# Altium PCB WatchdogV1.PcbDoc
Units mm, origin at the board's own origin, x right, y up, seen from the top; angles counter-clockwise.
Board outline 200 x 52 mm, 2 copper layers (Top Layer, Bottom Layer), stack 1.57 mm thick; 69 components, 43 nets, 240 pads, 392 vias.
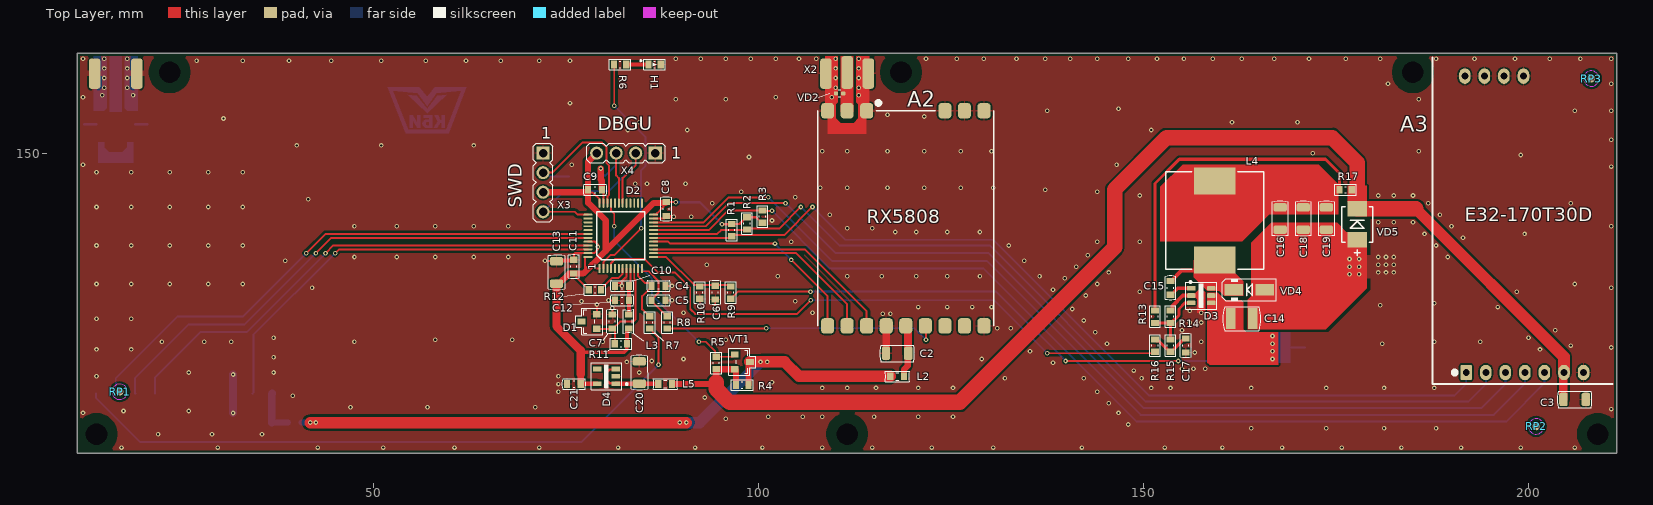
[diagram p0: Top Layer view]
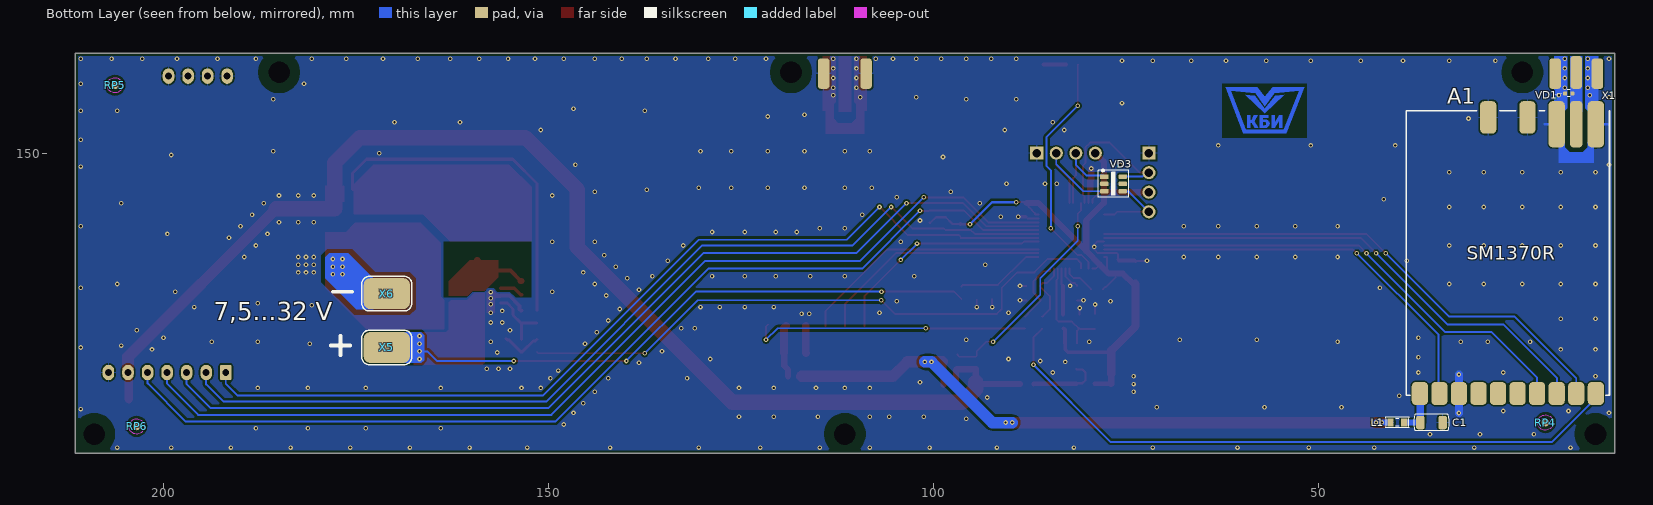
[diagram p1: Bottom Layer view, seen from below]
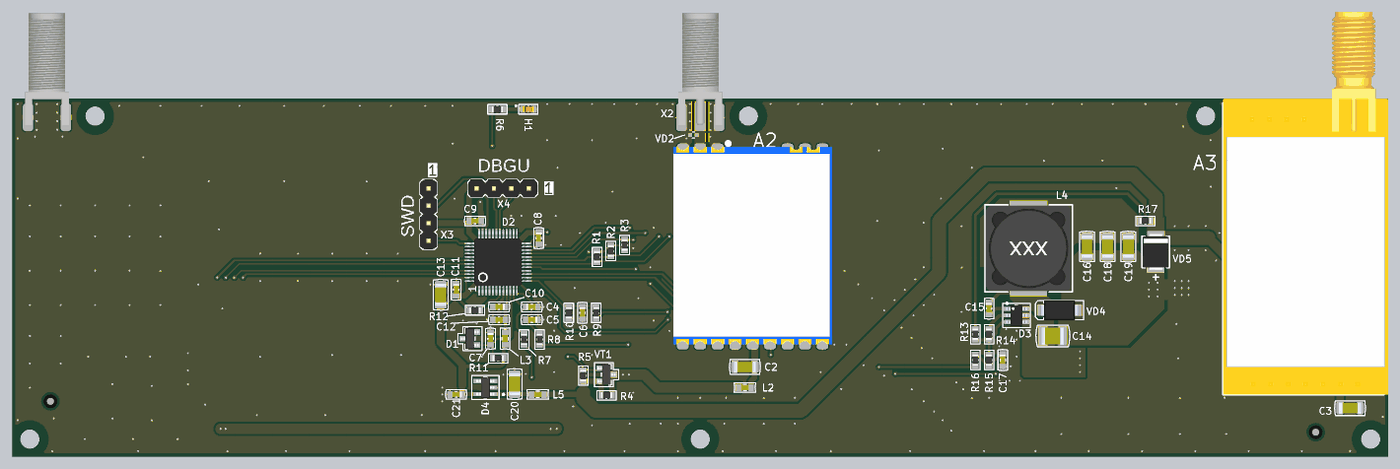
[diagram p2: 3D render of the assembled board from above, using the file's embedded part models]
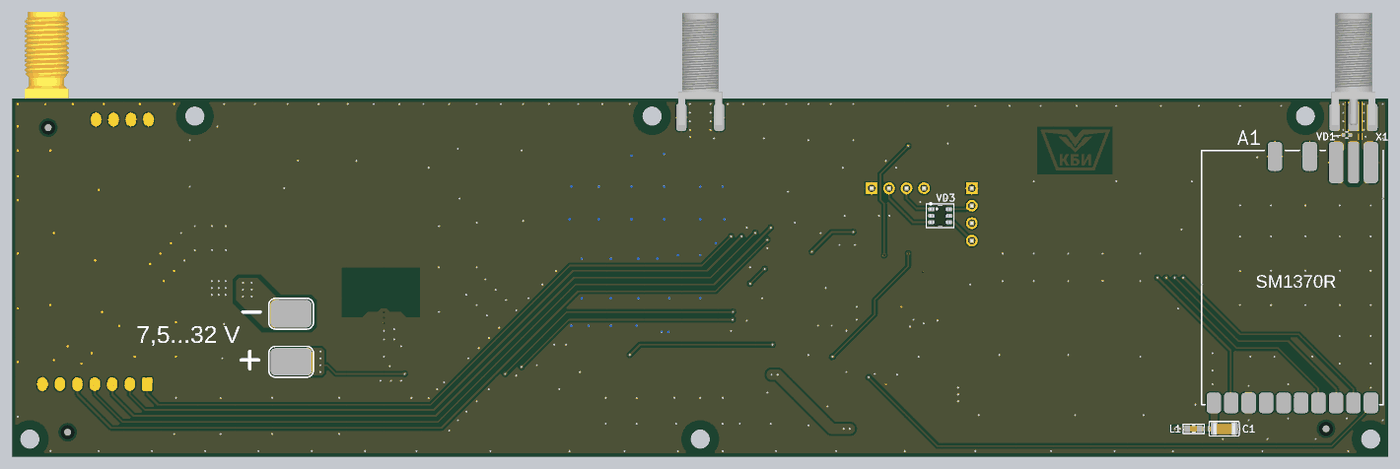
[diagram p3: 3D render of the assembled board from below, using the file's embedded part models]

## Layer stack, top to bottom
Top Solder: solder mask 0.0102, Solder Resist, Dk 3.5
Top Layer: signal copper 0.035
Dielectric 1: core 1.5, FR4 Tg135, Dk 4.5
Bottom Layer: signal copper 0.035
Bottom Solder: solder mask 0.0102, Solder Resist, Dk 3.5

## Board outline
11.5,111 211.5,111 211.5,163 11.5,163

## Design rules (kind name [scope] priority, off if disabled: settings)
AcuteAngle [All] p1: minimum=3.50000000000000E+0001 checktracksonly=FALSE
BoardOutlineClearance "BoardOutlineClearance 1" [All] p1 off: gap=0.25 ignorepadtopadclearanceinfootprint=FALSE except(0: Arc-SplitContinuation Track-SplitContinuation SMDPad-SplitContinuation THPad-SplitContinuation Via-SplitContinuation Fill-SplitContinuation Poly-SplitContinuation Region-SplitContinuation Text-SplitContinuation) // Milling
BoardOutlineClearance "BoardOutlineClearance 2" [All] p2: gap=0.4 ignorepadtopadclearanceinfootprint=FALSE except(0: Arc-SplitContinuation Track-SplitContinuation SMDPad-SplitContinuation THPad-SplitContinuation Via-SplitContinuation Fill-SplitContinuation Poly-SplitContinuation Region-SplitContinuation Text-SplitContinuation) // V-Cut
Clearance "Clearance 3 Oz" [All] p1 off: gap=0.35 ignorepadtopadclearanceinfootprint=FALSE except(0.25: Arc-Hole Track-Hole SMDPad-Hole THPad-Hole Via-Hole Fill-Hole Poly-Hole Region-Hole Text-Hole)
Clearance "Clearance 2 Oz" [All] p2 off: gap=0.3 ignorepadtopadclearanceinfootprint=FALSE except(0.25: Arc-Hole Track-Hole SMDPad-Hole THPad-Hole Via-Hole Fill-Hole Poly-Hole Region-Hole Text-Hole)
Clearance "Clearance-1 1 Oz" [All] p3: gap=0.2 ignorepadtopadclearanceinfootprint=FALSE except(0.25: Arc-Hole Track-Hole SMDPad-Hole THPad-Hole Via-Hole Fill-Hole Poly-Hole Region-Hole Text-Hole; 0.3: Arc-Fill Arc-Poly Arc-Region Track-Fill Track-Poly Track-Region Fill-Fill Fill-Poly Fill-Region Poly-Poly Poly-Region Region-Region) // Standart
Clearance "Clearance-2 1 Oz" [All] p4 off: gap=0.15 ignorepadtopadclearanceinfootprint=FALSE except(0.2: Arc-Fill Arc-Poly Track-Fill Track-Poly SMDPad-Fill SMDPad-Poly THPad-Fill THPad-Poly Via-Fill Via-Poly Fill-Fill Fill-Poly Poly-Poly; 0.25: Arc-Hole Track-Hole SMDPad-Hole THPad-Hole Via-Hole Fill-Hole Poly-Hole Region-Hole Text-Hole) // Advance
Clearance "Clearance-1 1/2 Oz" [All] p5 off: gap=0.125 ignorepadtopadclearanceinfootprint=FALSE except(0.2: Arc-Fill Arc-Poly Track-Fill Track-Poly SMDPad-SMDPad SMDPad-Fill SMDPad-Poly THPad-Fill THPad-Poly Via-Fill Via-Poly Fill-Fill Fill-Poly Poly-Poly Poly-Region Poly-Text; 0.25: Arc-Hole Track-Hole SMDPad-Hole THPad-Hole Via-Hole Fill-Hole Poly-Hole Region-Hole Text-Hole) // Standart
Clearance "Clearance-2 1/2 Oz" [All] p6 off: gap=0.1 ignorepadtopadclearanceinfootprint=FALSE except(0.15: Arc-Fill Arc-Poly Track-Fill Track-Poly SMDPad-SMDPad SMDPad-Fill SMDPad-Poly THPad-Fill THPad-Poly Via-Fill Via-Poly Fill-Fill Fill-Poly Poly-Poly Poly-Region Poly-Text; 0.25: Arc-Hole Track-Hole SMDPad-Hole THPad-Hole Via-Hole Fill-Hole Poly-Hole Region-Hole Text-Hole) // Advance
DiffPairsRouting "DiffPairsRouting 1 Oz" [All] p1: maxlimit=0.254 minlimit=0.2 mostfreqgap=0.254 toplayer_minwidth=0.2 toplayer_maxwidth=0.381 toplayer_prefwidth=0.381 bottomlayer_minwidth=0.2 bottomlayer_maxwidth=0.381 bottomlayer_prefwidth=0.381 maxuncoupledlength=12.7
DiffPairsRouting "DiffPairsRouting 1/2 Oz" [All] p2 off: maxlimit=0.254 minlimit=0.1 mostfreqgap=0.254 toplayer_minwidth=0.1 toplayer_maxwidth=0.381 toplayer_prefwidth=0.381 bottomlayer_minwidth=0.1 bottomlayer_maxwidth=0.381 bottomlayer_prefwidth=0.381 maxuncoupledlength=12.7
HoleSize "Minimum HoleSize" [IsPad] p1: absolutevalues=TRUE maxlimit=5.9 minlimit=0.6 maxpercent=80.000 minpercent=20.000
HoleSize "Minimum HoleSize VIA 1" [IsVia] p2: absolutevalues=TRUE maxlimit=5.9 minlimit=0.3 maxpercent=80.000 minpercent=20.000 // Standart
HoleSize "Minimum HoleSize VIA 2" [IsVia] p3 off: absolutevalues=TRUE maxlimit=5.9 minlimit=0.2 maxpercent=80.000 minpercent=20.000 // Advance
HoleToHoleClearance Hole2HoleClearance [All] p1: gap=0.25 allowstackedmicrovias=FALSE
MinimumAnnularRing "Minimum AR VIA Standart" [IsVia] p1: minimumring=0.15
MinimumAnnularRing "Minimum AR PAD Standart" [IsPAD] p2: minimumring=0.2
MinimumAnnularRing "Minimum AR VIA Advance" [IsVia] p3 off: minimumring=0.1
MinimumAnnularRing "Minimum AR PAD Advance" [IsPAD] p4 off: minimumring=0.15
MinimumSolderMaskSliver "SolderMask Bridge Standart" [All] p1: minsoldermaskwidth=0.15 // All Masks
MinimumSolderMaskSliver "SolderMask Bridge Advance" [All] p2: minsoldermaskwidth=0.1 // Mask LDI
PlaneClearance "PlaneClearance 3 Oz" [All] p1 off: clearance=0.35
PlaneClearance "PlaneClearance 2 Oz" [All] p2 off: clearance=0.3
PlaneClearance "PlaneClearance 1 Oz" [All] p3: clearance=0.2
PlaneClearance "PlaneClearance-1 1/2 Oz" [All] p4 off: clearance=0.2 // Standart
PlaneClearance "PlaneClearance-2 1/2 Oz" [All] p5 off: clearance=0.15 // Advance
PlaneConnect "TermalConnect 3 Oz" [All] p1 off: planeconnectstyle=Relief reliefexpansion=0.2 reliefentries=4 reliefconductorwidth=0.35 reliefairgap=0.35 // Standart
PlaneConnect "TermalConnect 2 Oz" [All] p2 off: planeconnectstyle=Relief reliefexpansion=0.2 reliefentries=4 reliefconductorwidth=0.3 reliefairgap=0.3 // Standart
PlaneConnect "TermalConnect-1 1 Oz" [All] p3: planeconnectstyle=Relief reliefexpansion=0.2 reliefentries=4 reliefconductorwidth=0.2 reliefairgap=0.2 // Standart
PlaneConnect "TermalConnect-2 1 Oz" [All] p4 off: pad.planeconnectstyle=Relief pad.reliefexpansion=0.15 pad.reliefentries=4 pad.reliefconductorwidth=0.2 pad.reliefairgap=0.2 via.planeconnectstyle=Direct via.reliefexpansion=0.15 via.reliefentries=4 via.reliefconductorwidth=0.15 via.reliefairgap=0.15 // Advance
PlaneConnect "TermalConnect-1 1/2 Oz" [All] p5 off: planeconnectstyle=Relief reliefexpansion=0.2 reliefentries=4 reliefconductorwidth=0.2 reliefairgap=0.2 // Standart
PlaneConnect "TermalConnect-2 1/2 Oz" [All] p6 off: pad.planeconnectstyle=Relief pad.reliefexpansion=0.15 pad.reliefentries=4 pad.reliefconductorwidth=0.15 pad.reliefairgap=0.15 via.planeconnectstyle=Direct via.reliefexpansion=0.15 via.reliefentries=4 via.reliefconductorwidth=0.15 via.reliefairgap=0.15 // Advance
PolygonConnect "PolygonConnect 3 Oz" [All] p1 off: thpad.connectstyle=Relief thpad.reliefconductorwidth=0.35 thpad.reliefentries=4 thpad.polygonreliefangle="90 Angle" thpad.airgapwidth=0.35 smdpad.connectstyle=Relief smdpad.reliefconductorwidth=0.35 smdpad.reliefentries=4 smdpad.polygonreliefangle="90 Angle" smdpad.airgapwidth=0.35 via.connectstyle=Direct via.reliefconductorwidth=0.254 via.reliefentries=4 via.polygonreliefangle="90 Angle" via.airgapwidth=0.254
PolygonConnect "PolygonConnect 2 Oz" [All] p2 off: thpad.connectstyle=Relief thpad.reliefconductorwidth=0.3 thpad.reliefentries=4 thpad.polygonreliefangle="90 Angle" thpad.airgapwidth=0.3 smdpad.connectstyle=Relief smdpad.reliefconductorwidth=0.3 smdpad.reliefentries=4 smdpad.polygonreliefangle="90 Angle" smdpad.airgapwidth=0.3 via.connectstyle=Direct via.reliefconductorwidth=0.254 via.reliefentries=4 via.polygonreliefangle="90 Angle" via.airgapwidth=0.254
PolygonConnect "PolygonConnect-1 1 Oz" [All] p3: thpad.connectstyle=Relief thpad.reliefconductorwidth=0.2 thpad.reliefentries=4 thpad.polygonreliefangle="90 Angle" thpad.airgapwidth=0.2 smdpad.connectstyle=Relief smdpad.reliefconductorwidth=0.2 smdpad.reliefentries=4 smdpad.polygonreliefangle="90 Angle" smdpad.airgapwidth=0.2 via.connectstyle=Direct via.reliefconductorwidth=0.254 via.reliefentries=4 via.polygonreliefangle="90 Angle" via.airgapwidth=0.254 // Standart
PolygonConnect "PolygonConnect-2 1 Oz" [All] p4 off: thpad.connectstyle=Relief thpad.reliefconductorwidth=0.15 thpad.reliefentries=4 thpad.polygonreliefangle="90 Angle" thpad.airgapwidth=0.15 smdpad.connectstyle=Relief smdpad.reliefconductorwidth=0.15 smdpad.reliefentries=4 smdpad.polygonreliefangle="90 Angle" smdpad.airgapwidth=0.15 via.connectstyle=Direct via.reliefconductorwidth=0.254 via.reliefentries=4 via.polygonreliefangle="90 Angle" via.airgapwidth=0.254 // Advance
PolygonConnect "PolygonConnect-1 1/2 Oz" [All] p5 off: thpad.connectstyle=Relief thpad.reliefconductorwidth=0.15 thpad.reliefentries=4 thpad.polygonreliefangle="90 Angle" thpad.airgapwidth=0.2 smdpad.connectstyle=Relief smdpad.reliefconductorwidth=0.2 smdpad.reliefentries=4 smdpad.polygonreliefangle="90 Angle" smdpad.airgapwidth=0.2 via.connectstyle=Direct via.reliefconductorwidth=0.254 via.reliefentries=4 via.polygonreliefangle="90 Angle" via.airgapwidth=0.254 // Standart
PolygonConnect "PolygonConnect-2 1/2 Oz" [All] p6 off: thpad.connectstyle=Relief thpad.reliefconductorwidth=0.125 thpad.reliefentries=4 thpad.polygonreliefangle="90 Angle" thpad.airgapwidth=0.15 smdpad.connectstyle=Relief smdpad.reliefconductorwidth=0.125 smdpad.reliefentries=4 smdpad.polygonreliefangle="90 Angle" smdpad.airgapwidth=0.15 via.connectstyle=Direct via.reliefconductorwidth=0.254 via.reliefentries=4 via.polygonreliefangle="90 Angle" via.airgapwidth=0.254 // Advance
RoutingCorners [All] p1 off: cornerstyle=45-Degree minsetback=2.54 maxsetback=2.54
RoutingVias [All] p1: holewidth=0.3 width=0.6 viastyle="Through Hole" minholewidth=0.2 minwidth=0.4 maxholewidth=5.9 maxwidth=6.4
SilkToSilkClearance Silk2SilkClearance [All] p1 off: silktosilkclearance=0.15
SilkToSolderMaskClearance Silk2SolderMaskClearance [IsPad] p1 off: minsilkscreentomaskgap=0.15 clearancetoexposedcopper=TRUE
SolderMaskExpansion SolderMaskExpansion-1 [All] p1: expansion=0.05 istentingtop=FALSE // Standart
SolderMaskExpansion "SolderMaskExpansion LDI" [All] p2: expansion=0.025 istentingtop=FALSE // Advance
UnRoutedNet [All] p1: checkbadconnections=TRUE
Width "Width 3 Oz" [All] p1 off: maxlimit=10 minlimit=0.35 preferedwidth=0.4 checkconnectedcopper=TRUE
Width "Width 2 Oz" [All] p2 off: maxlimit=10 minlimit=0.3 preferedwidth=0.35 minimp=50.000000 maximp=50.000000 favimp=50.000000 checkconnectedcopper=TRUE
Width "Width 1 Oz" [All] p3: maxlimit=10 minlimit=0.15 preferedwidth=0.2 checkconnectedcopper=TRUE
Width "Width 1/2 Oz" [All] p4 off: maxlimit=10 minlimit=0.1 preferedwidth=0.125 checkconnectedcopper=TRUE
20 further rules are at their usual default settings.

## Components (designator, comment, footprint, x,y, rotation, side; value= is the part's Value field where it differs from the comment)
A1 "Receiver SM1370R" SM1370R 36.82,118.774 r180 bottom locked
A2 "Receiver RX5808" RX5808 108.96,155.5 r0 top locked
A3 "Wireless Module E32-170T30D" E32-170T30D 199.54,121.5 r0 top locked
C1 "Конденсатор керамический 1206-X7R-25V-10uF±10%" CC1206 35.3,115 r180 bottom value=10uF
C2 "Конденсатор керамический 1206-X7R-25V-10uF±10%" CC1206 118,124 r180 top value=10uF
C3 "Конденсатор керамический 1206-X7R-25V-10uF±10%" CC1206 206,118 r0 top value=10uF
C4 "Конденсатор керамический 0603-NP0-50V-1000pF±5%" CC0603 87,132.75 r180 top value=1000pF
C5 "Конденсатор керамический 0603-NP0-50V-1000pF±5%" CC0603 87,130.875 r180 top value=1000pF
C6 "Конденсатор керамический 0603-X7R-50V-0.1uF±10%" CC0603 94.375,131.875 r90 top value=0.1uF
C7 "Конденсатор керамический 0603-X7R-50V-0.1uF±10%" CC0603 81,128.125 r270 top value=0.1uF
C8 "Конденсатор керамический 0603-X7R-50V-0.1uF±10%" CC0603 88,142.75 r270 top value=0.1uF
C9 "Конденсатор керамический 0603-X7R-50V-0.1uF±10%" CC0603 78.75,145.25 r0 top value=0.1uF
C10 "Конденсатор керамический 0603-X7R-50V-0.1uF±10%" CC0603 82.25,132.75 r180 top value=0.1uF
C11 "Конденсатор керамический 0603-X7R-50V-0.1uF±10%" CC0603 76,135.25 r90 top value=0.1uF
C12 "Конденсатор керамический 0603-X7R-16V-1uF±20%" CC0603 82.25,130.875 r180 top value=1uF
C13 "Конденсатор керамический 1206-X7R-25V-10uF±10%" CC1206 73.75,134.5 r90 top value=10uF
C14 "Конденсатор керамический 1210-X7R-63V-10uF±10%" CC1210 162.75,128.5 r0 top value=10uF
C15 "Конденсатор керамический 0603-X7R-50V-0.1uF±10%" CC0603 153.5,132.5 r270 top value=0.1uF
C16 "Конденсатор керамический 1206-X7R-25V-10uF±10%" CC1206 167.75,141.5 r270 top value=10uF
C17 "Конденсатор керамический 0603-X7R-16V-1uF±20%" CC0603 155.5,125 r270 top value=1uF
C18 "Конденсатор керамический 1206-X7R-25V-10uF±10%" CC1206 170.75,141.5 r270 top value=10uF
C19 "Конденсатор керамический 1206-X7R-25V-10uF±10%" CC1206 173.75,141.5 r270 top value=10uF
C20 "Конденсатор керамический 1206-X7R-25V-10uF±10%" CC1206 84.5,121.5 r90 top value=10uF
C21 "Конденсатор керамический 0603-X7R-16V-1uF±20%" CC0603 76,120 r180 top value=1uF
D1 "Микросхема LM4040AIM3-3.0" SOT-23 78,128.125 r180 top
D2 "Микросхема GD32E103CBT6" LQFP48_7x7 79.35,135 r90 top
D3 "Микросхема LMR14010ADDC" SOT-23-6#1 157.499,131.5 r0 top
D4 "Микросхема NCP114ASN330T1G" TSOP-5 80.25,121 r180 top value=3.3V
H1 "Светодиод 0603-RED-[100-150]-[50-150]MCD" LED0603_Red 86.5,161.5 r0 top value="100 MCD Red"
L1 "Дроссель BLM18PG331SN1D" CL0603 39.75,115 r0 bottom value=330R
L2 "Дроссель BLM18PG331SN1D" CL0603 118,121 r180 top value=330R
L3 "Дроссель BLM18AG102SN1D" CL0603 83.125,128.125 r270 top value=1000R
L4 "Дроссель SRR1260-470M" SRR1260 159.25,141.25 r90 top value="47 uH"
L5 "Дроссель BLM18AG102SN1D" CL0603 87.875,120 r180 top value=1000R
R1 "Резистор 0603-0.1W-47K±5%" CR0603 96.5,140 r90 top value=47K
R2 "Резистор 0603-0.1W-47K±5%" CR0603 98.5,140.875 r90 top value=47K
R3 "Резистор 0603-0.1W-47K±5%" CR0603 100.5,141.75 r270 top value=47K
R4 "Резистор 0603-0.1W-0R" CR0603 97.875,119.875 r0 top value=0
R5 "Резистор 0603-0.1W-47K±5%" CR0603 94.5,122.75 r90 top value=47K
R6 "Резистор 0603-0.1W-120R±5%" CR0603 82.001,161.5 r180 top value=120
R7 "Резистор 0603-0.1W-1K±5%" CR0603 85.875,128 r90 top value=1K
R8 "Резистор 0603-0.1W-1K±5%" CR0603 88.125,128 r90 top value=1K
R9 "Резистор 0603-0.1W-33K±1%" CR0603 96.375,131.875 r90 top value=33K
R10 "Резистор 0603-0.1W-3.9K±1%" CR0603 92.375,131.875 r90 top value=3.9K
R11 "Резистор 0603-0.1W-200R±5%" CR0603 82.125,125.25 r180 top value=200
R12 "Резистор 0603-0.1W-1K±5%" CR0603 78.75,132.25 r180 top value=1K
R13 "Резистор 0603-0.1W-43K±1%" CR0603 151.5,128.75 r90 top value=43K
R14 "Резистор 0603-0.1W-10K±1%" CR0603 153.5,128.75 r90 top value=10K
R15 "Резистор 0603-0.1W-36K±1%" CR0603 153.5,125 r270 top value=36K
R16 "Резистор 0603-0.1W-200R±5%" CR0603 151.5,125 r270 top value=200
R17 "Резистор 0603-0.1W-0R" CR0603 176.25,145.25 r0 top value=0
RP1 "Reper" Reper-Min 17,119 r0 top
RP2 "Reper" Reper-Min 201,114.5 r0 top
RP3 "Reper" Reper-Min 208.179,159.681 r0 top
RP4 "Reper" Reper-Min 20.5,115 r180 bottom
RP5 "Reper" Reper-Min 206.321,158.819 r180 bottom
RP6 "Reper" Reper-Min 203.5,114.5 r180 bottom
VD1 "Диод ESDAXLC6-1BT2" ESDAXLC6-1BT2 17.95,157.75 r180 bottom locked
VD2 "Диод ESDAXLC6-1BT2" ESDAXLC6-1BT2 110.05,157.75 r0 top locked
VD3 "Диодная сборка ESDA6V1BC6" SOT-23-6#2 76.6,146 r180 bottom
VD4 "Диод MBRA340T3G" "DO-214AC (SMA)" 163.75,132.25 r180 top
VD5 "Диод SMBJ5.0A" DO-214AA 177.75,140.75 r90 top
VT1 "Транзистор AO3401A" SOT-23 97.874,122.875 r0 top
X1 "Розетка KLS1-SMA060" SMA_Edge 16.5,160.475 r180 bottom locked
X2 "Розетка KLS1-SMA060" SMA_Edge 111.5,160.475 r0 top locked
X3 "Вилка PLS-4" PLS-4 72,150 r270 top
X4 "Вилка PLS-4" PLS-4 86.58,150 r180 top
X5 "Паяный контакт" PD-6X4 171,124.75 r270 bottom
X6 "Паяный контакт" PD-6X4 171,131.75 r270 bottom

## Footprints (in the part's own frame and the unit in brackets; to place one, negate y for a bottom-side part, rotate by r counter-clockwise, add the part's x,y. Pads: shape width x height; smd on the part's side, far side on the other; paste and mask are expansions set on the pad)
CC0603 [mm]
  rect 0.8x1 smd: 1(-0.9,0) 2(0.9,0)
  silkscreen extent -1.54,-0.71 1.54,0.7, body extent -0.81,-0.42 0.81,0.43, height 0.46
CC1206 [mm]
  rrect50% 1.1x1.75 smd: 1(-1.45,0) 2(1.45,0)
  silkscreen extent -2.25,-1.07 2.25,1.07, body extent -1.6,-0.8 1.6,0.8, height 1.3
CC1210 [mm]
  rect 1.25x2.75 smd: 1(-1.425,0) 2(1.425,0)
  silkscreen extent -2.44,-1.57 2.5,1.57, body extent -1.6,-1.25 1.6,1.25, height 1.3
CL0603 [mm]
  rect 0.8x1 smd: 1(-0.9,0) 2(0.9,0)
  silkscreen extent -1.56,-0.69 1.57,0.69, body extent -0.81,-0.42 0.81,0.43, height 0.46
CR0603 [mm]
  rect 0.8x1 smd: 1(-0.8,0) 2(0.8,0)
  silkscreen extent -1.4,-0.7 1.4,0.7, body extent -0.81,-0.42 0.81,0.43, height 0.46
DO-214AA [mm]
  rect 2x2.5 smd: A(-2,0) K(2,0)
  silkscreen extent -4.1,-2 2.3,2, body extent -2.65,-1.85 2.65,1.85, height 2.2
"DO-214AC (SMA)" [mm] "Molded Diode, 2-Leads, Body 4,2x2,7mm, IPC Medium Density"
  rect 2.4x1.55 smd: 1(-2,0) 2(2,0)
  silkscreen extent -3.5,-1.45 3.5,1.45, body extent -2.8,-1.45 2.8,1.45, height 2.4
E32-170T30D [mm]
  rrect30% 1.5x2 hole 0.9: 1(-7.62,0)
  oval 1.5x2 hole 0.9: 2(-5.08,0) 3(-2.54,0) 4(0,0) 5(2.54,0) 6(5.08,0) 7(7.62,0) 8(-0.18,38.5) 9(-2.72,38.5) 10(-5.26,38.5) 11(-7.8,38.5)
  silkscreen extent -12,-1.5 11.36,40.9, body extent -12,-1.5 12,54.2, height 8.27
ESDAXLC6-1BT2 [mm]
  rrect50% 0.55x0.5 smd: 1(0,0) 2(0.95,0)
  silkscreen extent 0.3,-0.45 0.65,0.45, body extent 0,-0.3 1,0.3, height 0.4
LED0603_Red [mm]
  rect 0.8x1 smd: 1(-0.8,0) 2(0.8,0)
  silkscreen extent -1.9,-0.7 1.4,0.7, body extent -0.81,-0.4 0.81,0.4, height 1.1
LQFP48_7x7 [mm]
  rect 1.2x0.25 smd: 1(0,0)
  oval 1.2x0.25 smd: 2(0,-0.5) 3(0,-1) 4(0,-1.5) 5(0,-2) 6(0,-2.5) 7(0,-3) 8(0,-3.5) 9(0,-4) 10(0,-4.5) 11(0,-5) 12(0,-5.5) 25(8.5,-5.5) 26(8.5,-5) 27(8.5,-4.5) 28(8.5,-4) 29(8.5,-3.5) 30(8.5,-3) 31(8.5,-2.5) 32(8.5,-2) 33(8.5,-1.5) 34(8.5,-1) 35(8.5,-0.5) 36(8.5,0)
  oval 0.25x1.2 smd: 13(1.5,-7) 14(2,-7) 15(2.5,-7) 16(3,-7) 17(3.5,-7) 18(4,-7) 19(4.5,-7) 20(5,-7) 21(5.5,-7) 22(6,-7) 23(6.5,-7) 24(7,-7) 37(7,1.5) 38(6.5,1.5) 39(6,1.5) 40(5.5,1.5) 41(5,1.5) 42(4.5,1.5) 43(4,1.5) 44(3.5,1.5) 45(3,1.5) 46(2.5,1.5) 47(2,1.5) 48(1.5,1.5)
  silkscreen extent 1.13,-5.86 7.36,0.37, body extent -0.25,-7.25 8.75,1.75, height 1.2
PD-6X4 [mm]
  rrect40% 4x6 smd: 1(0,0)
  silkscreen extent -2.25,-3.25 2.25,3.25
PLS-4 [mm]
  rect 1.7x1.7 hole 1.1: 1(0,0)
  round 1.7 hole 1.1: 2(2.54,0) 3(5.08,0) 4(7.62,0)
  silkscreen extent -1.27,-1.27 8.89,1.27, body extent -1.27,-1.27 8.89,1.27, height 8.8
Reper-Min [mm]
  round 1 smd mask+0.5: 0(0,0)
  Top Layer keep-out circle w0.1: c0,0 r1
RX5808 [mm]
  rrect50% 1.7x2 smd: 1(5.08,0) 1(15.24,0) 1(17.78,0) 1(20.32,0) 2(2.54,0) 3(0,0) 4(0,-27.94) 5(2.54,-27.94) 6(5.08,-27.94) 7(7.62,-27.94) 8(10.16,-27.94) 9(12.7,-27.94) 10(15.24,-27.94) 11(17.78,-27.94) 12(20.32,-27.94)
  silkscreen extent -1.27,-27.94 21.59,1.27, body extent -1.39,-28.19 21.71,0.51, height 3.11
SM1370R [mm]
  rrect50% 1.6x6 smd: 1(20.32,34.976)
  rrect50% 2.1x4.2 smd: 2(8.89,35.865) 2(13.97,35.865)
  rrect50% 2.1x6 smd: 2(17.78,34.976) 2(22.86,34.976)
  rrect50% 2.1x3 smd: 3(0,0) 4(2.54,0) 5(5.08,0) 6(7.62,0) 7(10.16,0) 8(12.7,0) 9(15.24,0) 10(17.78,0) 11(20.32,0) 12(22.86,0)
  silkscreen extent -1.78,-0.25 24.64,36.75, body extent -1.75,-0.25 24.65,36.75, height 3.3
SMA_Edge [mm] "Монтаж с торца платы"
  rrect50% 1.5x4.25 smd: 1(0,0)
  rrect50% 1.5x3.95 smd far side: 2(-2.75,-0.15) 2(2.75,-0.15)
  rrect50% 1.5x3.95 smd: 2(-2.75,-0.15) 2(2.75,-0.15)
  body extent -3.17,-1.3 3.18,14.96, height 3.83
SOT-23 [mm]
  rect 1x0.8 smd: 1(-0.975,0.95) 2(-0.975,-0.95) 3(1,0)
  silkscreen extent -1.75,-1.75 1.75,1.75, body extent -1.3,-1.5 1.3,1.5, height 1.12
SOT-23-6#1 [mm]
  rect 1.1x0.6 smd: 1(-1.3,0.95)
  rrect50% 1.1x0.6 smd: 2(-1.3,0) 3(-1.3,-0.95) 4(1.3,-0.95) 5(1.3,0) 6(1.3,0.95)
  silkscreen extent -2,-1.75 2,1.87, body extent -1.5,-1.52 1.5,1.52, height 1.45
SOT-23-6#2 [mm]
  rect 1.1x0.6 smd: 1(-1.2,0.95)
  rrect50% 1.1x0.6 smd: 2(-1.2,0) 3(-1.2,-0.95) 4(1.2,-0.95) 5(1.2,0) 6(1.2,0.95)
  silkscreen extent -2,-1.75 2,1.87, body extent -1.5,-1.52 1.5,1.53, height 1.45
SRR1260 [mm]
  rect 3.5x5.4 smd: 1(-5.15,0) 2(5.15,0)
  silkscreen extent -6.35,-6.35 6.35,6.35, body extent -6.25,-6.25 6.25,6.25, height 6.5
TSOP-5 [mm] "(SOT23-5)"
  rect 1.1x0.6 smd: 1(-1.2,0.95) 2(-1.2,0) 3(-1.2,-0.95) 4(1.2,-0.95) 5(1.2,0.95)
  silkscreen extent -2.75,-1.75 2,1.75, body extent -1.3,-1.5 1.3,1.5, height 1.12

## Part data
A1: library part SM1370R, "Аналоговый видеоприемник 1,2 ГГц"
A2: library part RX5808, "Аналоговый видеоприемник 5,8 ГГц"
A3: library part E32-170T30D, "Приемопередатчик 170 МГц"
C1 C2 C3 C13 C16 C18 C19 C20: library part CC1206-X7R-25V-10uF±10%, "Конденсатор керамический SMD", Manufacturer=Murata, Supplier Part Number 1=490-6518-6-ND
C4 C5: library part CC0603-NP0-50V-1000pF±5%, "Конденсатор керамический SMD", Manufacturer=Murata
C6 C7 C8 C9 C10 C11 C15: library part CC0603-X7R-50V-0.1uF±10%, "Конденсатор керамический SMD", Manufacturer=Samsung, Supplier Part Number 1=1276-1000-1-ND
C12 C17 C21: library part CC0603-X7R-16V-1uF±20%, "Конденсатор керамический SMD", Manufacturer=Samsung, Supplier Part Number 1=1276-6524-1-ND
C14: library part CC1210-X7R-50V-10uF±20%, "Конденсатор керамический SMD", Manufacturer=Murata
D1: library part LM4040AIM3-3.0, "ИОН 3.0V±0.1%; -40...+85C", Manufacturer=TI, Package=SOT-23
D2: library part GD32E103Cxxx, "ARM Cortrex-M4", Manufacturer=GigaDevice
D3: library part LMR14010ADDC, "DC/DC понижающий", Manufacturer=TI
D4: library part NCP114ASN330T, "LDO, 3.3V, 300mA, TSOP-5, -40...+85C; High Power Supply Ripple Rejection: 75 dB at 1 kHz", Manufacturer=ON
H1: library part LED-0603-RED, "0603 SMD-светодиод красный", Manufacturer=Kingbright, Supplier Part Number 1=KPT-1608SURC
L1 L2: library part BLM18PG331SN1D, "Чип-индуктивность подавления ЭМП. Типоразмер 0603", Manufacturer=Murata, Supplier Part Number 1=490-5222-1-ND
L3 L5: library part BLM18AG102SN1D, "Чип-индуктивность подавления ЭМП. Типоразмер 0603", Manufacturer=Murata, Supplier Part Number 1=490-1015-1-ND
L4: library part SRR1260, "SMD fix. ind.; 12.5x12.5x6.0mm", Manufacturer=Bourns
R1 R2 R3 R5: library part CR0603-0.1W-47K±5%, "Чип резистор", Manufacturer=Yageo, Voltage=75V
R4 R17: library part CR0603-0.1W-0R, "Чип резистор", Manufacturer=Yageo, Supplier Part Number 1=311-0.0GRCT-ND, Voltage=75V
R6: library part CR0603-0.1W-120R±5%, "Чип резистор", Manufacturer=Yageo, Voltage=75V
R7 R8 R12: library part CR0603-0.1W-1K±5%, "Чип резистор", Manufacturer=Yageo, Supplier Part Number 1=311-1.0KGRCT-ND, Voltage=75V
R9: library part CR0603-0.1W-33K±1%, "Чип резистор", Manufacturer=Yageo, Voltage=75V
R10: library part CR0603-0.1W-3.9K±1%, "Чип резистор", Manufacturer=Yageo, Voltage=75V
R11 R16: library part CR0603-0.1W-200R±5%, "Чип резистор", Manufacturer=Yageo, Supplier Part Number 1=311-200GRCT-ND, Voltage=75V
R13: library part CR0603-0.1W-43K±1%, "Чип резистор", Manufacturer=Yageo, Voltage=75V
R14: library part CR0603-0.1W-10K±1%, "Чип резистор", Manufacturer=Yageo, Voltage=75V
R15: library part CR0603-0.1W-36K±1%, "Чип резистор", Manufacturer=Yageo, Voltage=75V
VD1 VD2: library part ESDAXLC6-1BT2, "Single line ESD protection for high speed lines in 0402", Manufacturer=ST, Package=0402
VD3: library part ESDA6V1BC6, "4 TVS-диода с общей шиной", Manufacturer=ST, Supplier Part Number 1=33X1146
VD4: library part MBRA340T3G, "Диод шотки I=3А V=40В", Manufacturer=ON, Package="DO-214AC (SMA)", Supplier Part Number 1=58M8712
VD5: library part SMBJ5.0A, "TVS-диод (супрессор); 5V; Vbr 6.4V; 600W", Manufacturer=Vishay
VT1: library part AO3401A, "P-channel MOSFET; 30V; 4.2A; -55...+150C", Manufacturer=UMW
X1 X2: library part KLS1-SMA060, "SMA розетка монтаж с торца платы", Manufacturer=KLS
X3 X4: library part PLS-4_TABLE, "Вилка на плату однорядная прямая"

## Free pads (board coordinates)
  round 0 hole 2.8 unplated: 1(23.5,160.5) 2(14,113.5) 3(111.5,113.5) 4(118.5,160.5) 5(185,160.5) 6(209,113.5)

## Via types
v1: diameter 0.6, hole 0.3, Top Layer to Bottom Layer, tented both sides, 392 vias

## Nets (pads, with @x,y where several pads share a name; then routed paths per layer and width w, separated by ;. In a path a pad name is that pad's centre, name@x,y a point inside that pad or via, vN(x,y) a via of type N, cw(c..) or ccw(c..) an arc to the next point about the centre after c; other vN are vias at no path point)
3V3: C8.1 C9.1 C11.1 C13.1 C21.1 D2.1 D2.24 D2.36 D2.48 D4.5 L3.2 R1.2 R2.2 R3.2 R11.1 R12.2 X3.3 X4.4 | length 89.1
  Top Layer w0.25: C11.1@76.1,134.35 76.375,134.075 76.375,133.825 77.575,132.625 77.675,132.625 77.95,132.35 R12.2 ; 77.567,134.819 77.45,134.936 77.45,136.5 D2.48 ; C9.1@77.85,145.15 78.125,144.875 78.45,144.875 79.35,143.975 D2.36 ; 78.375,135.525 78.9,135 D2.1 ; D2.24 86.825,142 86.825,142.2 87.625,143 87.625,143.375 C8.1@87.775,143.525
  Top Layer w0.3: C8.1@87.9,143.525 88.012,143.638 89.237,143.638 v1(89.25,143.625) ; v1@95.269,140.769 R1.2@96.469,140.769 ; R1.2 97.525,140.8 98.4,141.675 R2.2 99.675,141.675 100.4,140.95 R3.2
  Top Layer w0.5: 76.875,124.375 76.9,124.35 77.125,124.125 82.5,124.125 82.875,124.5 82.875,125.2 R11.1 82.925,127.075 83.075,127.225 L3.2 ; v1(95.25,140.75) v1@95.269,140.769 ; R1.2@96.469,140.769 R1.2
  Top Layer w0.6: C21.1 76.95,120.05 D4.5
  Top Layer w0.8: X3.3 C9.1@77.575,144.92 ; C13.1 74.075,133.05 75.375,134.35 C11.1 76.1,134.35 77.2,134.35 78.375,135.525 80.15,137.3 ; C21.1 76.9,120.9 ; X4.4 77.85,148.89 C9.1 77.85,145.15 77.85,143.55 80.15,141.25 80.15,137.3 ; 84.703,141.853 80.15,137.3 ; 84.703,141.853 86.375,143.525 87.775,143.525 C8.1@87.9,143.525
  Top Layer w1.1: C13.1 73.75,127.5 76.875,124.375 ; 76.9,121.25 76.9,124.35
  Bottom Layer w0.3: v1(89.25,143.625) 92.375,143.625 v1(95.25,140.75)
DBG_UART_RX: D2.31 VD3.1 X4.3 | length 12.5
  Top Layer w0.25: X4.3 81.5,147.1 81.85,146.75 D2.31
  Bottom Layer w0.25: VD3.1 77.915,147.065 80.065,147.065 81.5,148.5 X4.3
DBG_UART_TX: D2.30 VD3.3 X4.2 | length 16.3
  Top Layer w0.25: D2.30 82.35,146.75 84.04,148.44 X4.2
  Bottom Layer w0.25: VD3.3 80.55,145.05 84.04,148.54 X4.2
GND: A1.2 A1.5 A2.1 A2.3 A2.7 A2.12 A3.7 A3.8 A3.9 A3.10 A3.11 C1.2 C2.2 C3.2 C4.1 C5.1 C6.1 C7.1 C8.2 C9.2 C10.2 C11.2 C12.2 C13.2 C14.2 C16.2 C17.2 C18.2 C19.2 C20.2 C21.2 D1.2 D2.8 D2.23 D2.35 D2.44 D2.47 D3.2 D4.2 H1.2 R10.1 R14.2 VD1.1 VD2.1 VD3.2 VD3.5 VD4.1 VD5.A X1.2 X2.2 X3.1 X4.1 X6.1 | length 48.5
  Top Layer w0.25: v1(72.25,136) 72.275,135.975 73.725,135.975 C13.2 ; C11.2 76,136.854 76.146,137 D2.47 78.625,137 79.125,137.5 v1(79.125,137.813) 79.125,138.125 78.75,138.5 D2.44 ; D1.2 79,129.1 v1(79,130.331) ; C9.2 79.85,145.05 D2.35 ; v1(80.5,130.875) C12.2 ; C7.1 v1(81,129.875) ; C10.2 81.35,132.85 81.625,133.125 81.975,133.125 82.85,134 D2.8 ; D2.23 87.775,141.5 C8.2@88,141.725 ; C5.1 v1(88.75,130.875) ; C4.1 v1(88.75,132.75) ; v1(92.375,130) R10.1 ; v1(94.375,130) C6.1
  Top Layer w0.5: C13.2 73.85,136.05 75.9,136.05 C11.2 ; C9.2@79.638,145.262 C9.2 ; C8.2@88,141.725 88.012,141.737 88.987,141.737 v1(89,141.75) ; R14.2 153.6,129.55 153.75,129.7 153.75,130.15 155.1,131.5 D3.2 156.249,131.45 157.173,131.45 157.473,131.15 v1(157.5,131.15)
  Top Layer w0.8: v1(79.5,148) 79.5,146.565 79.638,146.428 C9.2@79.638,145.262
  Top Layer w1: C2.2 116.565,124.015 116.565,127.545 A2.7 ; A3.7@207.16,121.115 A3.7
  Bottom Layer w0.3: 12.375,153.75 A1.2@13.96,153.75 ; A1.2@19.04,153.75 20.625,153.75
  Bottom Layer w0.5: X6.1 175,131.75
  Bottom Layer w1: v1(31.74,116.24) A1.5 v1(31.74,121.24)
  other v1: 17.25,111.75 29.75,111.75 42.75,111.75 51.25,111.75 60.5,111.75 71.5,111.75 81.75,111.75 91.75,111.75 100.5,111.75 108.25,111.75 114.75,111.75 122.5,111.75 130.5,111.75 142,111.75 152.75,111.75 160.25,111.75 168,111.75 175.75,111.75 183.5,111.75 191.25,111.75 199,111.75 206,111.75 22,113.5 29,113.5 35.5,113.5 164,114.25 173.75,114.25 181.25,114.25 188,114.25 148,114.75 95.75,115.5 101.25,115.75 105.75,115.75 108.25,115.75 115,115.75 120.75,115.75 125.25,115.75 12.25,116.25 146.75,116.25 17.5,116.5 26,116.5 210.75,116.75 47,117 57,117 71,117 145.5,117.5 93,118.25 39.5,118.5 74,119 144,119 108.25,119.5 111.5,119.5 115.25,119.5 120.75,119.5 125.25,119.5 151,119.5 153.5,119.5 164,119.5 173.75,119.5 181.25,119.5 187.75,119.5 74,120 101.75,120.25 132,120.75 142.25,120.75 149.75,120.75 14,121 74,121 26,121.5 37,121.5 84.5,121.5 148.75,121.75 155,122 156.5,122 158,122 138.25,122.75 82.875,122.875 86.125,123 90.25,123.25 129,123.25 37,123.5 156.65,124.1 135.25,124.25 14,124.5 18.5,124.5 201.5,124.5 210.75,124.75 205.5,125 145.25,125.25 181,125.25 22.5,125.5 28,125.5 31.5,125.5 47.5,125.5 79.75,125.5 157.5,125.5 187.75,125.5 193.75,125.5 58,125.75 68,125.75 95.75,125.75 37,126 200,126 143.75,126.75 155,127 203.5,127 131,127.25 132.75,127.25 156,128 157.5,128 142.25,128.25 14,128.5 18.5,128.5 116.125,129.125 117.125,129.125 90.25,129.25 107,129.25 157.5,129.25 156,129.5 140.75,129.75 120.75,130 124.5,130 127.75,130 130.25,130 196,130 180.75,130.25 157.5,130.35 187.75,130.5 77,130.75 104.75,130.75 142.5,131.5 157.5,131.95 149.5,132 198.5,132 138.25,132.25 42,132.5 210.75,132.5 82.25,132.75 14,133 18.5,133 23.5,133 28.5,133 33,133 144,133 206,133 139.75,133.75 102.5,134 111.5,134 116,134 120.5,134 124.5,134 128.75,134 136.5,134 176.75,134.25 178,134.25 145.5,134.5 180.5,134.5 181.5,134.5 182.5,134.5 141.25,135.25 176.75,135.25 178,135.25 93.25,135.5 180.5,135.5 181.5,135.5 182.5,135.5 38.5,136 134.5,136 176.75,136.25 178,136.25 47.5,136.5 53,136.5 58,136.5 63,136.5 67.5,136.5 180.5,136.5 181.5,136.5 182.5,136.5 189.5,136.5 142.75,136.75 14,138 18.5,138 23.5,138 28.5,138 33,138 132.5,138 188,138 104.25,138.5 144,138.5 149.5,138.5 191.5,139 186.5,139.5 199.5,139.5 117.75,139.75 120.5,139.75 124.5,139.75 128.75,139.75 111.5,140.25 114.75,140.25 47.5,140.5 53,140.5 58,140.5 63,140.5 67.5,140.5 190,140.5 210.75,140.5 180.5,141 182.5,141 185,141 101.75,141.25 91.25,141.75 109.25,142 188.5,142 14,143 18.5,143 23.5,143 28.5,143 33,143 94,143.5 187,143.5 205.5,143.5 41.5,144 104.75,144.25 149.5,144.5 180.5,144.5 182.5,144.5 185,144.5 97.75,145 144,145 137.25,145.25 108,145.5 111.5,145.5 116.75,145.5 121.5,145.5 126.25,145.5 130.5,145.5 84,146 85.5,146 90.5,146 14,147.5 18.5,147.5 23.5,147.5 28.5,147.5 33,147.5 210.75,148.25 12.25,148.5 75.75,148.5 146.5,148.5 98.75,149.5 199,149.75 172,150 108.25,150.25 111.5,150.25 116.75,150.25 121.5,150.25 126.25,150.25 130.25,150.25 185.75,150.25 40,151 51,151 63,151 210.75,151.75 83,153 90.75,153 151,153 84.5,154 161.5,154 170,154 30.5,154.5 121.5,154.75 116.75,155 137.5,155.5 206,155.5 210.75,155.5 146.75,155.75 75.5,156.5 89.25,157 95.75,157 185.75,157 12.25,157.25 102.25,157.25 109.5,157.25 14.75,157.5 18.75,157.5 113,157.5 15,158.5 18,158.5 110,158.5 113,158.5 181.75,159 210.75,159 15,159.75 18,159.75 110,159.75 113,159.75 15,161 18,161 110,161 113,161 27,162 33,162 39,162 44.5,162 51,162 56.75,162 62,162 66.5,162 71.5,162 75.5,162 12.25,162.25 15,162.25 18,162.25 89.25,162.25 92.5,162.25 95.75,162.25 99,162.25 102.25,162.25 105.25,162.25 107.5,162.25 110,162.25 113,162.25 121.75,162.25 125.75,162.25 129.25,162.25 133.5,162.25 137.25,162.25 140.5,162.25 144,162.25 148,162.25 151.75,162.25 155.25,162.25 159,162.25 162.75,162.25 167,162.25 171.5,162.25 176.25,162.25 180.75,162.25 188,162.25 193,162.25 198.25,162.25 202.75,162.25 206.75,162.25 210.75,162.25
LED_R: D2.2 R6.2 | length 30.7
  Top Layer w0.25: D2.2 79.85,135.85 80.75,136.75 81.25,136.75 v1(84.75,140.25) ; R6.2 81.25,161.451 v1(81.25,156.15)
  Bottom Layer w0.25: v1(81.25,156.15) 85.3,152.1 85.3,148.3 84.75,147.75 v1(84.75,140.25)
LORA_AUX: A3.5 D2.20 R3.1 | length 131.6
  Top Layer w0.25: D2.20 93.5,140 96.05,142.55 R3.1 100.55,142.5 v1(101.75,142.5)
  Bottom Layer w0.25: v1(101.75,142.5) 109.25,135 129.25,135 149.125,115.125 197.125,115.125 202.08,120.08 A3.5
LORA_M0: A3.1 D2.18 R1.1 | length 119.4
  Top Layer w0.25: D2.18 R1.1@96.5,139 ; R1.1 96.65,139.35 103.35,139.35 v1(107,143)
  Bottom Layer w0.25: v1(107,143) 111.25,138.75 130.5,138.75 150.75,118.5 190.375,118.5 191.92,120.045 A3.1
LORA_M1: A3.2 D2.19 R2.1 | length 122.5
  Top Layer w0.25: D2.19 94.625,139.5 95.125,140 98.425,140 98.65,140.225 102.725,140.225 v1(105.5,143)
  Bottom Layer w0.25: v1(105.5,143) 110.5,138 130,138 150.25,117.75 192.25,117.75 194.46,119.96 A3.2
LORA_RXD: A3.3 D2.21 | length 125.7
  Top Layer w0.25: D2.21 93.125,140.5 96.125,143.5 v1(103.5,143.5)
  Bottom Layer w0.25: v1(103.5,143.5) 110,137 129.875,137 150,116.875 193.875,116.875 197,120 A3.3
LORA_TXD: A3.4 D2.22 | length 129.4
  Top Layer w0.25: D2.22 92.875,141 96.125,144.25 v1(101.25,144.25)
  Bottom Layer w0.25: v1(101.25,144.25) 109.5,136 129.625,136 149.625,116 195.5,116 199.54,120.04 A3.4
NetA1_1: A1.1 VD1.2 X1.1
NetA1_3: A1.3 C1.1 L1.1 | length 5.9
  Bottom Layer w0.8: C1.1 L1.1
  Bottom Layer w1: C1.1 36.75,118.704 A1.3
NetA2_2: A2.2 VD2.2 X2.1
NetA2_8: A2.8 C2.1 L2.1 | length 6.9
  Top Layer w0.8: L2.1 118.9,121.9 119.375,122.375 119.375,123.925 C2.1
  Top Layer w1: A2.8 119.4,127.28 119.4,124.05 C2.1
NetC4_2: C4.2 D2.11 R7.2 | length 8.2
  Top Layer w0.25: D2.11 84.35,134.025 85.25,133.125 85.825,133.125 86.1,132.85 C4.2 86.1,132.65 84.875,131.425 84.875,129.7 85.775,128.8 R7.2
NetC5_2: C5.2 D2.12 R8.2 | length 8.9
  Top Layer w0.25: D2.12 84.85,134.65 85.725,134.65 87,133.375 87,131.875 86.1,130.975 C5.2 86.1,130.775 87.75,129.125 87.75,129.075 88.025,128.8 R8.2
NetC6_2: C6.2 D2.13 R9.2 R10.2 | length 11.6
  Top Layer w0.25: D2.13 88,136.5 91.625,132.875 94.375,132.875 96.175,132.875 R9.2
NetC7_2: C7.2 D1.1 D2.10 R11.2 | length 14.3
  Top Layer w0.25: D1.1 80.95,127.175 C7.2 C7.2@81.05,127.225 ; R11.2 81.325,126.95 C7.2@81.05,127.225 ; D2.10 83.85,133.65 84,133.5 84,128.375 83.75,128.125 82,128.125 81.1,127.225 C7.2@81.05,127.225
NetC15_1: C15.1 D3.6 L4.1 VD4.2 | length 6.9
  Top Layer w0.5: C15.1@153.6,133.4 154.95,134.75 L4.1@157.9,134.75
  Top Layer w0.8: C15.1 C15.1@153.6,133.4 ; L4.1@157.9,134.75 L4.1
NetC15_2: C15.2 D3.1 | length 3.1
  Top Layer w0.5: C15.2 153.6,131.6 154.45,132.45 D3.1
NetC16_1: C16.1 C18.1 C19.1 L4.2 R13.2 R17.1 | length 45.6
  Top Layer w0.4: R13.2 151.5,146.05 154.65,149.2 173.65,149.2 175.45,147.4 R17.1 174.5,145.25
NetC17_1: C17.1 R15.2 R16.1 | length 5.4
  Top Layer w0.4: R16.1 151.7,125.6 152,125.6 153.4,124.2 R15.2 153.6,124.2 155.1,125.7 155.3,125.7 C17.1
NetC20_1: C20.1 D4.1 D4.3 L5.2 | length 9.3
  Top Layer w0.3: D4.1 81.375,120.125 80.625,120.125 80.25,120.5 80.25,121.5 80.632,121.882 81.382,121.882 D4.3
  Top Layer w0.6: D4.1 C20.1 84.525,120.025 86.95,120.025 L5.2
NetD2_7: D2.7 R12.1 | length 4.4
  Top Layer w0.25: R12.1 79.55,132.35 80.95,133.75 81.8,133.75 82.35,134.3 D2.7
NetD3_3: D3.3 R13.1 R14.1 R15.1 | length 8.4
  Top Layer w0.4: R13.1 R14.1 ; R15.1 R14.1 ; D3.3 155.4,130.55 154.6,129.75 154.6,128.95 153.6,127.95 R14.1
NetH1_1: H1.1 R6.1 | length 2.9
  Top Layer w0.5: R6.1 H1.1
NetL1_2: L1.2 L2.2 R4.2 VT1.3 | length 87.5
  Top Layer w0.8: R4.2 98.675,122.776 98.774,122.875 VT1.3
  Top Layer w1.5: v1(41.75,115) v1(42.5,115) v1(89.75,115) v1(90.625,115) ; VT1.3 100.25,122.875 v1(101.125,122.875) 103.375,122.875 105.25,121 L2.2
  Bottom Layer w0.8: L1.2 v1(41.75,115) v1(42.5,115)
  Bottom Layer w1.5: v1(89.75,115) v1(90.625,115) 92.375,115 v1(100.25,122.875) v1(101.125,122.875)
nRX_ON: D2.33 R5.2 VT1.1 | length 28.8
  Top Layer w0.25: D2.33 80.85,142.525 81.25,142.125 v1(81.25,140.5) ; v1(92.25,125.5) 93.125,125.5 94.375,124.25 94.375,123.675 R5.2 96.624,123.55 VT1.1
  Bottom Layer w0.25: v1(81.25,140.5) 81.25,138.625 86.125,133.75 86.125,131.625 v1(92.25,125.5) v1@92.375,125.375
nVCC_UP: D2.4 R16.2 | length 79.8
  Top Layer w0.25: D2.4 80.85,135.725 81.375,136.25 85.125,136.25 86.877,134.498 89.127,134.498 91.125,132.5 91.125,129.75 91.75,129.125 105,129.125 106.763,130.888 v1(106.779,130.888) ; v1(137.5,124) 151.3,124 R16.2
  Bottom Layer w0.25: v1(106.779,130.888) 130.612,130.888 v1(137.5,124)
RSSI_1G2: A1.12 R7.1 | length 85.3
  Top Layer w0.25: R7.1 87,126.075 v1(87,122.5)
  Bottom Layer w0.25: A1.12 13.96,118.165 19.625,112.5 77,112.5 v1(87,122.5)
RSSI_5G8: A2.9 R8.1 | length 36.4
  Top Layer w0.25: R8.1 100.825,127.2 100.875,127.25 v1(101,127.25) ; A2.9@121.461,127.759 A2.9 121.75,127.47 v1(121.75,125.75)
  Bottom Layer w0.25: v1(101,127.25) 120.25,127.25 v1(121.75,125.75)
RX1G2_CS1: A1.11 D2.42 | length 71.1
  Top Layer w0.25: v1(41.25,137) 43.75,139.5 D2.42
  Bottom Layer w0.25: A1.11 16.5,120.75 24.5,128.75 33,128.75 v1(41.25,137)
RX1G2_CS2: A1.10 D2.43 | length 68.4
  Top Layer w0.25: v1(42.5,137) 44.5,139 D2.43
  Bottom Layer w0.25: A1.10 19,118.814 19,120.75 26,127.75 33.25,127.75 v1(42.5,137)
RX1G2_CS3: A1.9 D2.45 | length 65.4
  Top Layer w0.25: v1(43.75,137) 44.75,138 D2.45
  Bottom Layer w0.25: A1.9 21.625,118.819 21.625,120.875 27.5,126.75 33.5,126.75 v1(43.75,137)
RX1G2_S1: A1.4 D2.46 | length 55.7
  Top Layer w0.25: v1(45,137) 45.5,137.5 D2.46
  Bottom Layer w0.25: A1.4 34.375,118.869 34.375,126.375 v1(45,137)
SPI_CLK: A2.6 D2.15 | length 32.9
  Top Layer w0.25: D2.15 106,137.5 114.04,129.46 A2.6
SPI_MOSI: A2.4 D2.17 | length 29.4
  Top Layer w0.25: D2.17 88.25,138.5 88.5,138.25 v1(102.125,138.25) ; v1(104.25,136.125) 108.96,131.415 A2.4
  Bottom Layer w0.25: v1(102.125,138.25) v1(104.25,136.125)
SPI_SS: A2.5 D2.14 | length 30.7
  Top Layer w0.25: D2.14 104.875,137 111.5,130.375 A2.5
SWCLK: D2.37 VD3.4 X3.4 | length 10.5
  Top Layer w0.25: X3.4 76.12,142.38 76.5,142 D2.37
  Bottom Layer w0.25: X3.4 74.62,145 75.35,145 VD3.4
SWDIO: D2.34 VD3.6 X3.2 | length 21.2
  Top Layer w0.25: X3.2 73.21,147.46 77.1,151.35 79.65,151.35 80.25,150.75 80.25,148.7 80.55,148.4 80.55,144.55 80.35,144.35 D2.34
  Bottom Layer w0.25: X3.2 72.361,147.46 72.871,146.95 VD3.6
Uin: C14.1 D3.4 D3.5 R9.1 X5.1 | length 78.8
  Top Layer w0.25: R9.1 97.3,132 v1(106.75,132) ; v1(139.875,123) v1(154.5,123)
  Bottom Layer w0.25: v1(106.75,132) 130.875,132 v1(139.875,123) ; v1(154.5,123) 164.5,123 165.75,124.25 v1(166.75,124.25) ; 167.25,124.75 X5.1
  other v1: 166.75,123.25 166.75,125.25 166.75,126.25
VCC: A3.6 C3.1 L5.1 R4.1 R5.1 R17.2 VD5.K VT1.2 | length 163.3
  Top Layer w0.8: L5.1 94.25,120 94.5,120.25 R5.1 94.6,121.95 94.625,121.925 VT1.2 96.999,121.925 97.075,121.849 R4.1
  Top Layer w1.1: C3.1 204.55,121.43 A3.6 ; 204.6,123.55 204.62,123.53
  Top Layer w1.5: 185.4,142.75 204.6,123.55 ; A3.6 204.62,123.53
  Top Layer w2: 94.5,120.25 94.5,119.375 96.25,117.625 126.125,117.625 146.25,137.75 146.25,145.25 153,152 174.5,152 177.75,148.75 VD5.K 185.4,142.75
VDDA: C10.1 C12.1 D2.9 L3.1 | length 6.1
  Top Layer w0.25: L3.1 L3.1@83.15,129.05 ; C10.1 83.35,132.95 D2.9
  Top Layer w0.5: L3.1@83.15,129.05 83.15,131 C10.1
pads on no net: A1.6 A1.7 A1.8 A2.10 A2.11 D1.3 D2.3 D2.5 D2.6 D2.16 D2.25 D2.26 D2.27 D2.28 D2.29 D2.32 D2.38 D2.39 D2.40 D2.41 D4.4 RP1.0 RP2.0 RP3.0 RP4.0 RP5.0 RP6.0

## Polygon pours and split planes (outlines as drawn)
GND on Top Layer "GND_L01_P000" (solid, pour order 0): 11.5,163 11.5,111 211.5,111 211.5,163
GND on Bottom Layer "GND_L02_P001" (solid, pour order 1): 11.5,163 11.5,111 211.5,111 211.5,163

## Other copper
Top Layer:
  pour cut-out: 23.5,157.75 cw(c23.5,160.5) 20.75,160.5 cw(c23.5,160.5) 23.5,163.25 cw(c23.5,160.5) 26.25,160.5 cw(c23.5,160.5)
  pour cut-out: 14,110.75 cw(c14,113.5) 11.25,113.5 cw(c14,113.5) 14,116.25 cw(c14,113.5) 16.75,113.5 cw(c14,113.5)
  pour cut-out: 209,110.75 cw(c209,113.5) 206.25,113.5 cw(c209,113.5) 209,116.25 cw(c209,113.5) 211.75,113.5 cw(c209,113.5)
  pour cut-out: 185,157.75 cw(c185,160.5) 182.25,160.5 cw(c185,160.5) 185,163.25 cw(c185,160.5) 187.75,160.5 cw(c185,160.5)
  pour cut-out: 118.5,157.75 cw(c118.5,160.5) 115.75,160.5 cw(c118.5,160.5) 118.5,163.25 cw(c118.5,160.5) 121.25,160.5 cw(c118.5,160.5)
  pour cut-out: 111.5,110.75 cw(c111.5,113.5) 108.75,113.5 cw(c111.5,113.5) 111.5,116.25 cw(c111.5,113.5) 114.25,113.5 cw(c111.5,113.5)
  pour cut-out: 109,153.25 109.5,153.25 109.5,152.75 113.5,152.75 113.5,153.25 114,153.25 114,163 109,163
  region net VCC: 176.5,143.7 176.5,145.75 179,145.75 179,143.7
  pour cut-out: 151.5,128.75 154.5,128.75 154.5,129.75 155.75,131 158.75,131 163,126.75 174,126.75 179.5,132.25 179.5,133.75 176.5,133.75 176.25,134 176.25,136.5 176.5,136.75 179.5,136.75 179.5,142.5 151.5,142.5
  region net Uin: 158.3,131.85 159.65,131.85 160.6,130.9 160.608,130.908 162.692,130.908 162.95,130.65 162.95,127.15 163.35,126.75 167.5,126.75 167.5,122.5 158.6,122.5 158.3,122.8
  region net GND: 163.55,127.125 163.55,130.95 164,131.4 164,138.35 166.6,140.95 175.15,140.95 176.35,139.75 179,139.75 179,132.45 173.675,127.125
  region net GND: 156.5,131.8 156.75,131.8 157.2,132.25 157.65,132.25 158,131.9 158,129.25 157,129.25 157,131 156.8,131.2 156.5,131.2
  region net NetC15_1: 158.3,132.15 156.55,133.9 156.55,136.1 160.2,136.1 162.95,133.35 162.95,131.5 160.5,131.5 159.85,132.15
  region net NetC16_1: 175.3,142.05 166.3,142.05 162.8,138.55 152.2,138.55 152.2,145.6 155.1,148.5 172.75,148.5 175.3,145.95
  region net GND: 110.05,156.6 110.05,154.5 110.65,153.9 112.35,153.9 112.95,154.5 112.95,156.6 114,156.6 114,152.5 109,152.5 109,156.6
  region net GND: 113.8,155.5 112.7,156.6 112.7,162.6 114.35,162.6 114.35,155.5
  region net GND: 109.2,155.5 110.3,156.6 110.3,162.6 108.65,162.6 108.65,155.5
  region net NetA2_2: 110.7,162.6 110.7,155.4 112.3,155.4 112.3,162.6
Bottom Layer:
  pour cut-out: 118.5,157.75 cw(c118.5,160.5) 115.75,160.5 cw(c118.5,160.5) 118.5,163.25 cw(c118.5,160.5) 121.25,160.5 cw(c118.5,160.5)
  pour cut-out: 185,157.75 cw(c185,160.5) 182.25,160.5 cw(c185,160.5) 185,163.25 cw(c185,160.5) 187.75,160.5 cw(c185,160.5)
  pour cut-out: 209,110.75 cw(c209,113.5) 206.25,113.5 cw(c209,113.5) 209,116.25 cw(c209,113.5) 211.75,113.5 cw(c209,113.5)
  pour cut-out: 111.5,110.75 cw(c111.5,113.5) 108.75,113.5 cw(c111.5,113.5) 111.5,116.25 cw(c111.5,113.5) 114.25,113.5 cw(c111.5,113.5)
  pour cut-out: 14,110.75 cw(c14,113.5) 11.25,113.5 cw(c14,113.5) 14,116.25 cw(c14,113.5) 16.75,113.5 cw(c14,113.5)
  pour cut-out: 23.5,157.75 cw(c23.5,160.5) 20.75,160.5 cw(c23.5,160.5) 23.5,163.25 cw(c23.5,160.5) 26.25,160.5 cw(c23.5,160.5)
  region net GND: 56.9,157.375 57,157.375 57,157.325 56.9,157.325
  region net GND: 56.95,157.343 56.95,156.1 56.96,156.1 58.158,157.792 61.4,158.125 59.437,153.014 54.463,153.014 52.501,158.125 55.743,157.792 56.94,156.1 56.95,156.1 56.95,157.343 55.952,158.57 51.856,158.57 54.16,152.57 59.74,152.57 62.044,158.57 57.948,158.57
  region net GND: 55.095,154.275 55.664,153.275 56.063,153.275 56.063,154.931 55.664,154.931 55.664,153.925 55.642,153.925 55.07,154.931 54.67,154.931 54.67,153.275 55.07,153.275 55.07,154.275
  region net GND: 54.438,157.555 56.95,155.2 59.463,157.555 58.284,157.443 56.961,155.77 56.939,155.77 55.62,157.443
  pour cut-out: 51.5,159 62.5,159 62.5,152 51.5,152
  region net GND: 59.23,153.275 59.23,154.931 58.831,154.931 58.831,154.29 58.678,154.29 58.359,154.931 57.876,154.931 58.331,154.166 57.819,153.275 58.291,153.275 58.642,153.929 58.831,153.929 58.831,153.275
  region net GND: 57.607,153.275 57.206,153.582 57.001,153.582 56.932,153.589 56.873,153.607 56.81,153.649 56.776,153.689 56.751,153.739 56.739,153.798 56.739,153.854 56.748,153.899 56.776,153.955 56.808,153.99 56.856,154.022 56.921,154.045 56.994,154.053 57.206,154.053 57.206,154.36 57,154.36 56.91,154.356 56.83,154.346 56.755,154.329 56.69,154.308 56.611,154.273 56.556,154.24 56.491,154.188 56.42,154.104 56.388,154.049 56.36,153.977 56.342,153.891 56.339,153.808 56.348,153.718 56.368,153.641 56.414,153.547 56.481,153.461 56.548,153.403 56.63,153.355 56.709,153.321 56.789,153.298 56.868,153.284 57.007,153.275
  region net GND: 57.607,153.275 57.607,154.931 56.488,154.931 56.488,154.623 57.206,154.623 57.206,153.582
  pour cut-out: 13.75,150.5 14.5,150.5 14.5,149.75 18.5,149.75 18.5,150.5 19.25,150.5 19.25,163 13.75,163
  pour cut-out: 168,134.5 172.5,134.5 175.5,137.5 178.75,137.5 179.5,136.75 179.5,133.25 175.25,129 168,129 167.25,129.75 167.25,133.75
  pour cut-out: 152.25,138.5 152.25,131.25 154.25,131.25 155,132 156.625,132 157.125,132.5 157.875,132.5 158.375,132 159.875,132 160.625,131.25 163.625,131.25 163.625,138.5
  region net GND: 176,137 178.5,137 179,136.5 179,133.75 175,129.75 172.75,129.75 172.75,133.75
  region net Uin: 169.05,126.75 166.55,126.75 166.15,126.35 166.15,123.1 166.5,122.75 169.05,122.75
  region net GND: 15,155.5 15.3,155.8 15.3,162.6 13.625,162.6 13.625,155.5
  region net GND: 18,155.5 17.7,155.8 17.7,162.6 19.375,162.6 19.375,155.5
  region net GND: 15,151.425 15,150.775 15.65,150.125 17.35,150.125 18,150.775 18,151.425 18.75,151.425 18.75,148.775 14.25,148.775 14.25,151.425
  region net NetA1_1: 15.7,162.6 15.7,155.4 17.3,155.4 17.3,162.6

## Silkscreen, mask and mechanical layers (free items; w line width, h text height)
Top Overlay:
  lines w0.15: 74.625,131.375 77.25,131.75 ; 75.75,130.375 80.625,130.625 ; 79.875,125.75 80.5,126.625 ; 80.125,124.125 80.725,124.55 ; 83.71,133.45 85.875,134.125 ; 83.815,126.559 85,125.625 ; 86.575,126.6 87.625,125.625 ; 107.75,157.25 109.25,157.75
  text "DBGU" at 79.125,152.407 h3
  text "SWD" at 69.843,142.875 h3 r90
Bottom Overlay:
  lines w0.15: 18.45,157.7 19.504,157.583
  lines w0.5: 175.5,132 178,132 ; 175.75,125 178.25,125 ; 177,123.75 177,126.25
  text "7,5...32 V" at 193.5,127.507 h4
Top Solder:
  region: 112.2,158.05 112.8,158.05 112.8,156.75 112.2,156.75
  region: 110.2,162.65 112.8,162.65 112.8,158.35 110.2,158.35
Bottom Solder:
  region: 15.8,158 15.2,158 15.2,157.05 15.8,157.05
  region: 15.2,162.65 17.8,162.65 17.8,158.35 15.2,158.35
Board:
  the board outline again, w0.1
Крепеж слота батареи:
  drawing of 244 lines, arcs and shapes, not listed
  text "R6" at 24.75,169.516 h1.5
  text "D2.2" at 24.75,166.5 h1.5
  text "R3" at 31.5,164.267 h1.5

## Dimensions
47,85.5 to 10,91 on Крепеж слота батареи
47,85.5 to 111.5,85.5 on Крепеж слота батареи
28.5,166.5 to 84.5,165.5 on Крепеж слота батареи
84.5,165.5 to 111.5,176.702 on Крепеж слота батареи
47.5,86 to 18,83 on Крепеж слота батареи
14.1,105 to 18,83 on Крепеж слота батареи
47,86 to 43.5,91 on Крепеж слота батареи
18,91 to 16.5,91 on Крепеж слота батареи
18,91 to 15,87 on Крепеж слота батареи
7,91 to 216,91 on Крепеж слота батареи
22.843,168 to 28.5,172 on Крепеж слота батареи
28.5,166.5 to 7,164 on Крепеж слота батареи
25.5,160.5 to 11.5,163 on Крепеж слота батареи
11.5,163 to 11.5,111 on Крепеж слота батареи
25.5,160.5 to 16,113.5 on Крепеж слота батареи
118.5,158.5 to 211.5,163 on Крепеж слота батареи
185,158.5 to 211.5,163 on Крепеж слота батареи
13,165 to 20,165 on Крепеж слота батареи
7,164 to 16.5,176.756 on Крепеж слота батареи
23.5,158.5 to 11.5,163 on Крепеж слота батареи
16,113.5 to 11.5,111 on Крепеж слота батареи
14,115.5 to 11.5,111 on Крепеж слота батареи
45,141.5 to 47.75,132.5 on Крепеж слота батареи
50.5,141.5 to 51.75,133.5 on Крепеж слота батареи
45,141.5 to 50.5,141.5 on Крепеж слота батареи
43.75,133.5 to 51.75,133.5 on Крепеж слота батареи
12,165 to 11,168 on Крепеж слота батареи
